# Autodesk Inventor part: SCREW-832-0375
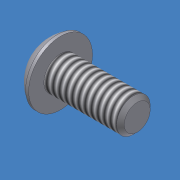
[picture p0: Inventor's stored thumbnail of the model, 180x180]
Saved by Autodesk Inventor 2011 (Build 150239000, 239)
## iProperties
Created: 2007-08
Part Number: SCREW-832-0375
Material: Stainless Steel
Document SubType Name: Modeling
Density: 8.08 g/cm^3
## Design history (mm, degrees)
feature "Base1"
thread "Thread1" dims "d0" = 25.4, "d1" = 0
body "Solid1"
